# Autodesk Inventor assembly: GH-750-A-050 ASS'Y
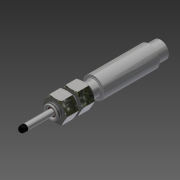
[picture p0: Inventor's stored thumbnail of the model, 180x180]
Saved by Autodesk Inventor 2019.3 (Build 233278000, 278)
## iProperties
Created: 2018-10
Part Number: GH-750-A-050 ASS'Y
Document SubType Name: Weldment
Designer: Justin
Weld Material: Stainless Steel
Author: Justin
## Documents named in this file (4)
- C:\Users\Justin\Documents\CAD Drawings\The Sensor Connection\3D\LVDT\GH SERIES\GH-750-A-XXXX\GH-750-A-050\GH-750-A-050 ASS'Y.iam
- C:\Users\Justin\Documents\Inventor\Content Center Files\R2019\en-US\AS 2465(1)\AS 2465 - 1_2  UNF(1).ipt
- C:\Users\Justin\Documents\CAD Drawings\The Sensor Connection\3D\LVDT\GH SERIES\GH-750-A-XXXX\GH-750-A-050\GH-750-A-050 SHAFT_SW.ipt
- C:\Users\Justin\Documents\CAD Drawings\The Sensor Connection\3D\LVDT\GH SERIES\GH-750-A-XXXX\GH-750-A-050\GH-750-A-050 Housing_SW.ipt
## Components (4 placed, 3 different names)
1. AS 2465 - Inch 1/2  UNF:1 — Mate:14, Mate:15, Angle:5
2. AS 2465 - Inch 1/2  UNF:2 — Mate:14, Mate:15
3. GH-750-A-050 Housing_SW:2 — Mate:20, Cylindrical:1
4. GH-750-A-050 SHAFT_SW:1 — Mate:20, Cylindrical:1
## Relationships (5: Mate 3, Angle 1, CylindricalJoint 1)
- Mate:14: AS 2465 - Inch 1/2  UNF:1 ↔ AS 2465 - Inch 1/2  UNF:2
- Mate:15: AS 2465 - Inch 1/2  UNF:1 ↔ AS 2465 - Inch 1/2  UNF:2
- Angle:5: AS 2465 - Inch 1/2  UNF:1
- Mate:20: GH-750-A-050 Housing_SW:2 ↔ GH-750-A-050 SHAFT_SW:1
- Cylindrical:1: GH-750-A-050 Housing_SW:2 ↔ GH-750-A-050 SHAFT_SW:1
